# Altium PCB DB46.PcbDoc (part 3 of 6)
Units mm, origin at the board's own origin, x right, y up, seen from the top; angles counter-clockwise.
Board outline 82.2 x 113.2 mm, 8 copper layers (Top Layer, MidLayer1, MidLayer2, GND, MidLayer3, VCC, MidLayer4, Bottom Layer), stack 1.576 mm thick; 186 components, 477 nets, 1727 pads, 1538 vias.
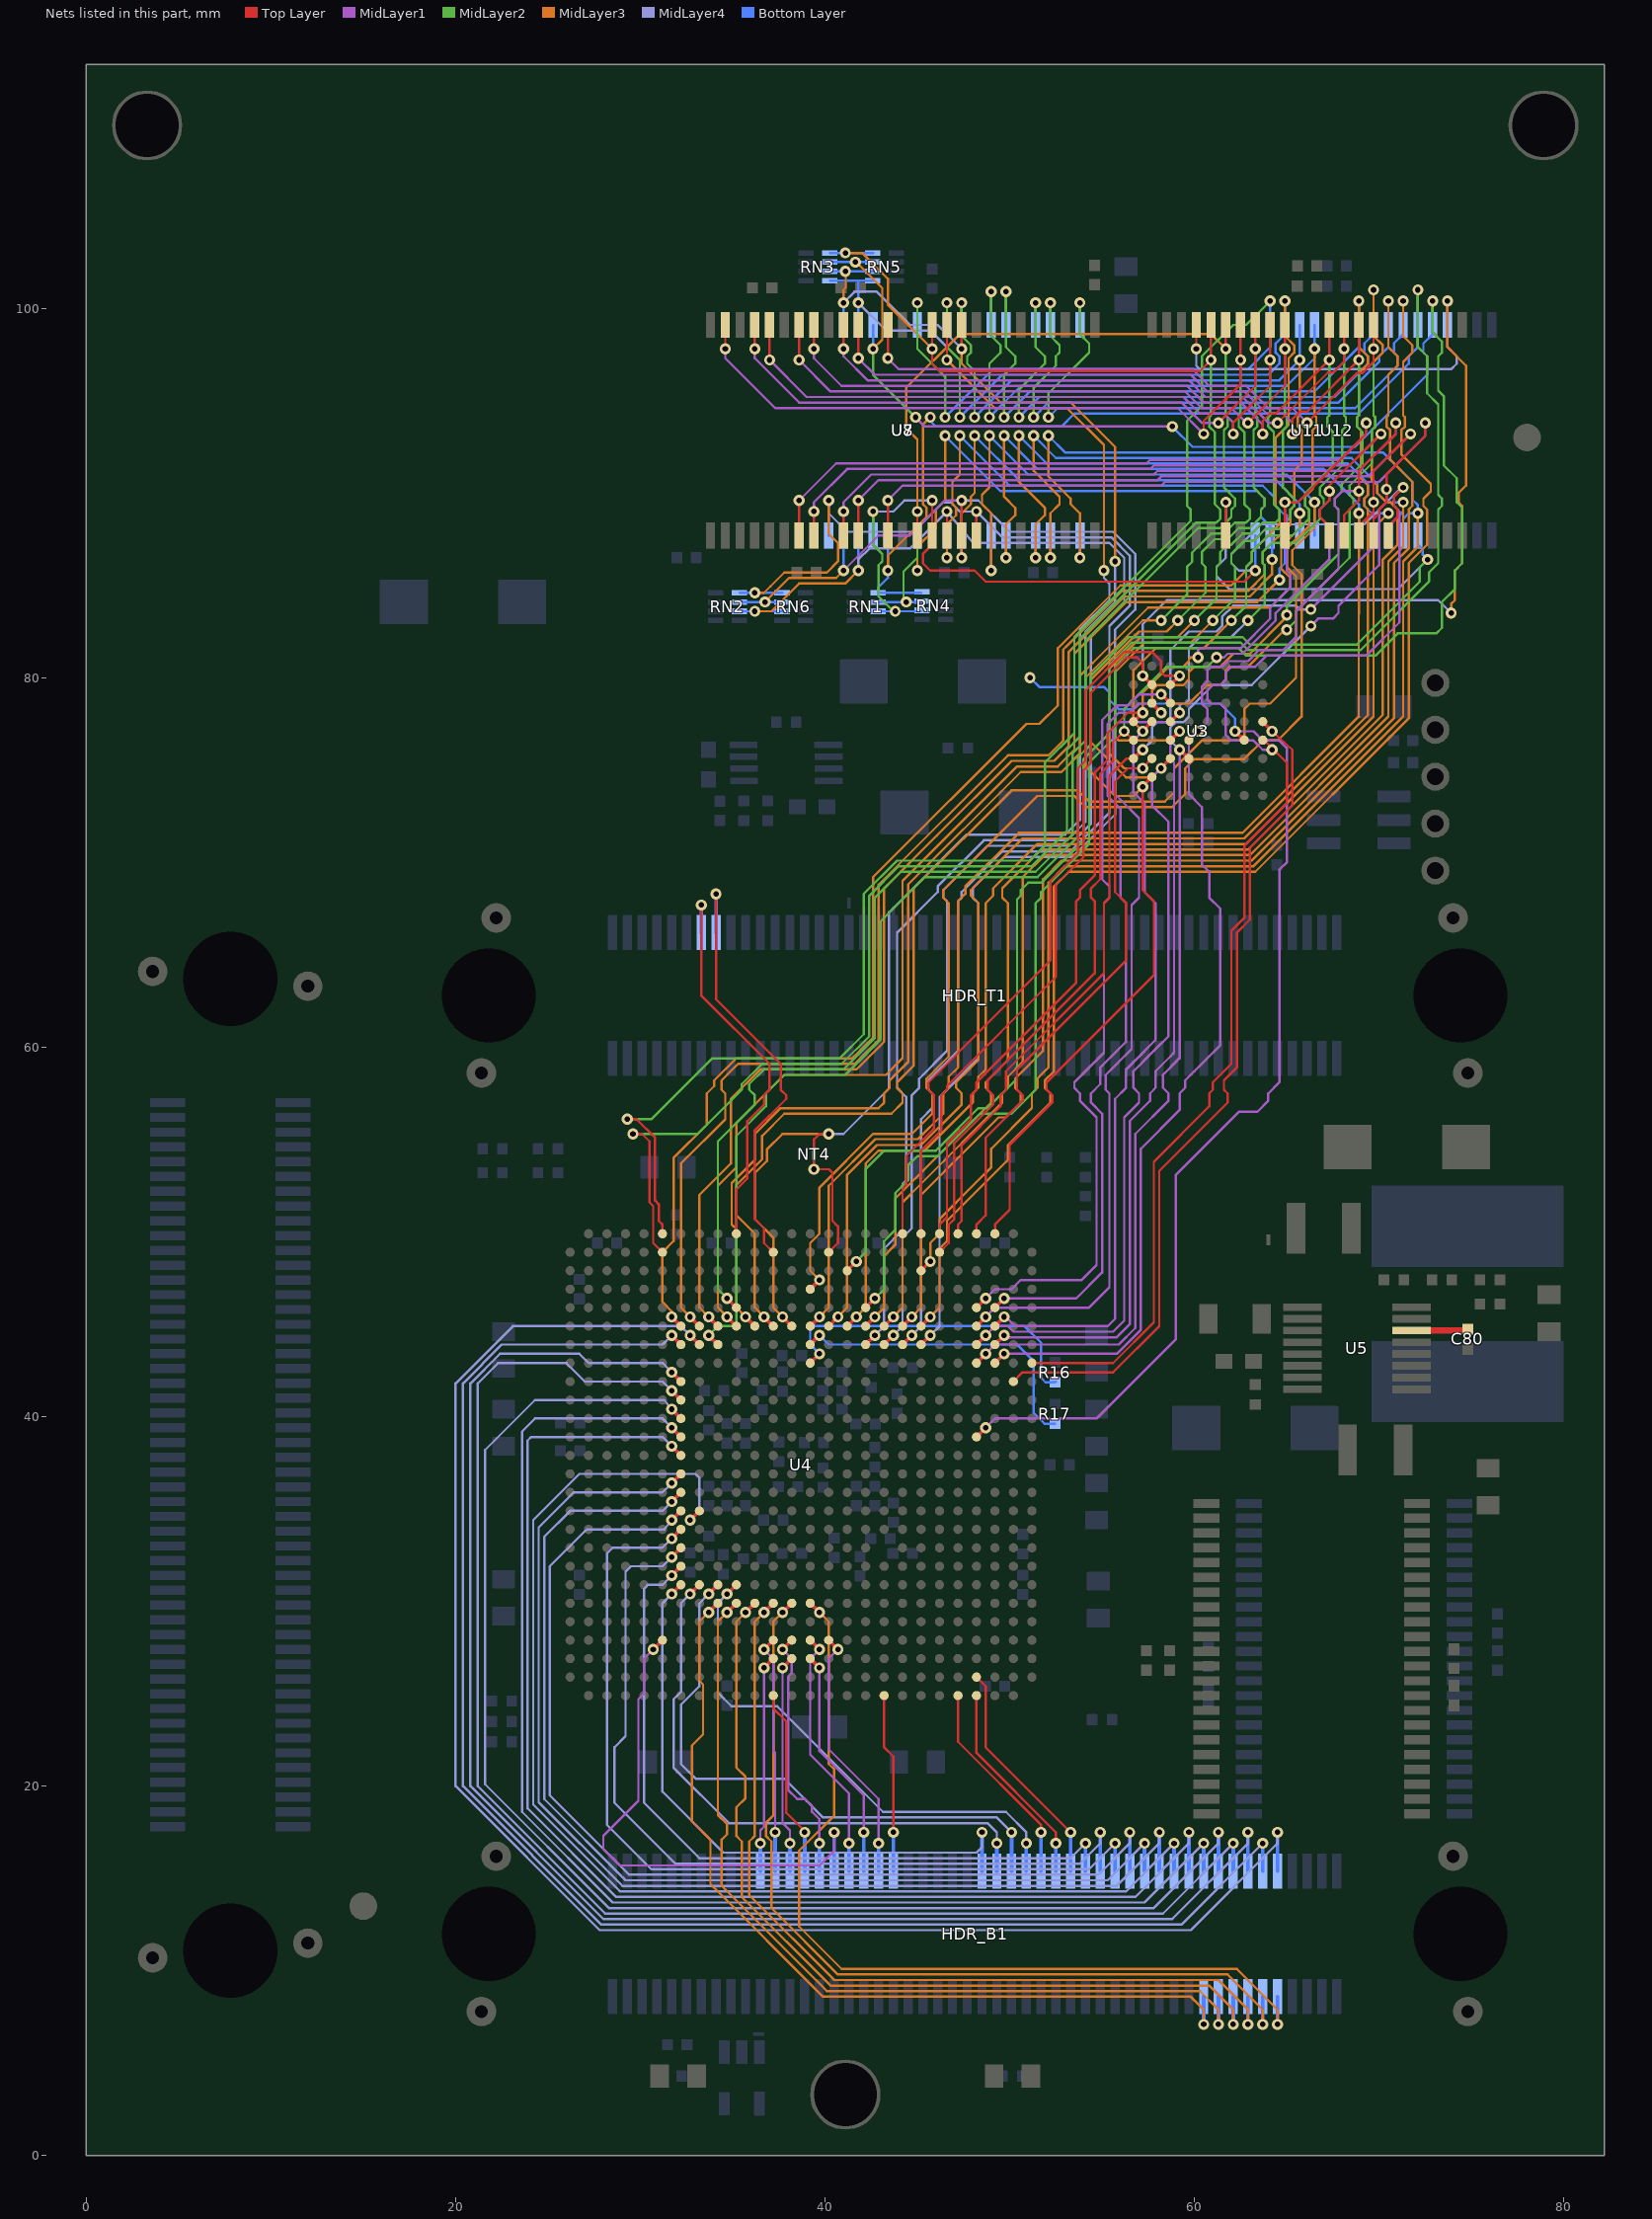
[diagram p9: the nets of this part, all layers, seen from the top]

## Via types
v1: diameter 0.6, hole 0.3, Top Layer to Bottom Layer, 904 vias
v2: diameter 0.6, hole 0.3, Top Layer to Bottom Layer, tented both sides, 506 vias
v3: diameter 0.7, hole 0.4, Top Layer to Bottom Layer, 127 vias
v4: diameter 0.6, hole 0.3, Top Layer to Bottom Layer, tented top, 1 vias

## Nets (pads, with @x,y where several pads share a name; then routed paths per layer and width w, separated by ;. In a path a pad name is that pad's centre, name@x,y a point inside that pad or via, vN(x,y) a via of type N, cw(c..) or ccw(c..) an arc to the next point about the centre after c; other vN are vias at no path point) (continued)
BUS_D3: U3.H4 U4.A21 U7.7 U11.10 | length 93.8
  Top Layer w0.127: U7.7@38.6,87.7 v2(38.6,89.6) ; U4.A21@46.2,49.9 46.2,50.4 46.6,50.8 46.6,51.5 46.6,51.8 46.6,54.8 47.9,56.1 47.9,57.4 48.2,57.7 48.2,58.1 53.6,63.5 53.6,67.9 53.8,68.1 53.8,68.5 54.6,69.3 54.6,74.859 55.3,75.559 55.3,77 56.4,78.1 v1(57.2,78.1) ; U11.10@64.9,87.7 v1(64.9,89.5) 65.6,89.5 69.3,93.2 v2(69.3,93.8)
  Top Layer w0.2: U3.H4@56.7,77.625 v1@57.187,78.112
  MidLayer1 w0.127: v2(38.6,89.6) 40.6,91.6 57.4,91.6 57.6,91.8 67.9,91.8 69.3,93.2 v2(69.3,93.8) ; v1(60.2,81.1) 60.2,81.5 60.3,81.6 62.5,81.6 64.1,83.2 64.1,83.8 65.2,84.9 65.2,85.6 65,85.8 65,88.8 64.9,88.9 v1(64.9,89.5)
  MidLayer3 w0.127: v1(57.2,78.1) 57.2,79.2 57.3,79.3 58.6,80.6 59.4,80.6 59.7,80.9 59.7,81 59.8,81.1 v1(60.2,81.1)
BUS_D4: U3.H5 U4.B21 U7.8 U11.13 | length 94.7
  Top Layer w0.127: U7.8@39.4,87.7 v2(39.4,89) ; U4.B21@46.2,48.9 46.7,49.4 ; 46.7,49.5 46.7,49.4 ; U3.H5@56.7,76.625 v1(56.2,77.1) 55.6,76.5 55.6,75.5 54.9,74.8 54.9,69.1 54.4,68.6 54.4,68.1 54.6,67.9 54.6,64 48.8,58.2 48.8,57.7 49.1,57.4 49.1,56.9 47,54.8 47,51.8 47,51.5 47,50.7 46.7,50.4 46.7,50.3 46.7,49.4 ; U11.13@67.3,87.7 67.3,88.2 66.8,88.7 66.8,89.1 67.3,89.6 v1(67.3,90.1) 67.3,90.4 v2(70.1,93.2)
  MidLayer1 w0.127: v2(39.4,89) 39.4,89.5 41.2,91.3 57.6,91.3 57.8,91.5 68.4,91.5 v2(70.1,93.2) ; v1(61.2,81.1) 61.6,81.1 61.8,81.3 62.6,81.3 64.4,83.1 64.4,83.5 67.3,86.4 67.3,88.2 66.8,88.7 66.8,89.1 67.3,89.6 v1(67.3,90.1)
  MidLayer2 w0.127: v1(56.2,77.1) 56.2,78.3 58.5,80.6 60.7,80.6 v1(61.2,81.1)
BUS_D5: U3.E5 U4.H24 U7.10 U11.14 | length 104.8
  Top Layer w0.127: U7.10@41,87.7 v2(41,89) ; U11.14@68.1,87.7 68.1,88.8 68.9,89.6 68.9,91.2 70.9,93.2 v2(70.9,93.8)
  Top Layer w0.2: U4.H24@49.2,42.9 v1(49.7,43.4) ; U3.E5@59.7,76.625 v1(60.2,77.1)
  MidLayer1 w0.127: v2(41,89) 41,89.5 42.5,91 57.8,91 58,91.2 68.9,91.2 70.9,93.2 v2(70.9,93.8) ; v1(49.7,43.4) 52.8,43.4 53.1,43.4 55.8,43.4 57.1,44.7 57.1,54.5 59.2,56.6 59.2,57.5 59.5,57.8 59.5,58.2 60,58.7 61.4,60.1 61.4,67.5 60.8,68.1 60.8,69.5 60.4,69.9 60.4,73 59.7,73.7 59.7,76.6 60.7,77.6 60.7,78.3 60.4,78.6 60.4,79.5 60.7,79.8 60.7,80.4 60.9,80.6 61.5,80.6 61.8,80.9 62.9,80.9 63.5,81.5 64.8,81.5 65.5,82.2 65.5,83.6 67.8,85.9 67.8,89.1 67.6,89.3 67.6,89.7 68,90.1 v1(68.9,90.1)
BUS_D6: U3.H6 U4.A22 U7.11 U11.15 | length 93
  Top Layer w0.127: U7.11@41.8,87.7 v2(41.8,89.6) ; U4.A22@47.2,49.9 47.2,50.4 47.4,50.6 47.4,51.5 47.4,51.8 47.4,54.7 49.5,56.8 49.5,57.4 49.8,57.7 49.8,58.7 55.1,64 55.1,67.8 55.4,68.1 55.4,74.7 56.325,75.625 U3.H6@56.7,75.625 ; U11.15@68.9,87.7 68.9,88.2 69.7,89 v1(69.7,89.5) 69.7,91.2 v2(71.7,93.2)
  Top Layer w0.2: U3.H6@56.7,75.625 57.187,76.112 v1@57.2,76.125
  MidLayer1 w0.127: v2(41.8,89.6) 42.9,90.7 58,90.7 58.2,90.9 69.4,90.9 v2(71.7,93.2) ; v1(66.3,83.7) 69.7,87.1 v1(69.7,89.5)
  MidLayer4 w0.127: v1(57.2,76.1) 57.7,76.6 57.7,77.3 58,77.6 58.5,77.6 58.7,77.8 58.7,81.5 59.7,82.5 61.2,82.5 61.5,82.8 61.5,83.3 62.1,83.9 65.5,83.9 65.7,83.7 v1(66.3,83.7)
BUS_D7: U3.E6 U4.H23 U7.13 U11.16 | length 104.7
  Top Layer w0.127: U7.13@43.4,87.7 v2(43.4,89.6) ; U11.16@69.7,87.7 69.7,88.6 70,88.9 70,89.1 70.4,89.5 70.4,91 72.5,93.1 v2(72.5,93.8)
  Top Layer w0.2: U4.H23@48.2,42.9 v1(48.7,43.4) ; v1@59.2,76.125 U3.E6@59.7,75.625
  MidLayer1 w0.127: v2(43.4,89.6) 44.2,90.4 58.2,90.4 58.4,90.6 70,90.6 72.5,93.1 v2(72.5,93.8) ; v1(48.7,43.4) 49.2,43.9 52.8,43.9 53.1,43.9 55.9,43.9 56.8,44.8 56.8,55.3 58.6,57.1 58.6,57.5 58.3,57.8 58.3,58.5 59.2,59.4 59.2,68.6 ; 59.2,68.1 v1(59.2,76.1) v1@59.2,76.125 ; v1(66.3,82.8) 66.7,83.2 67.5,83.2 67.8,83.5 67.8,83.9 70,86.1 70,89.1 70.4,89.5 v1(70.4,90.2)
  MidLayer4 w0.127: v1(59.2,76.1) 58.7,76.6 58.7,77.3 59,77.6 59.4,77.6 59.7,77.9 59.7,78.3 61,79.6 63.1,79.6 v1(66.3,82.8)
BUS_D8: U3.F3 U4.E23 U7.42 U11.29 | length 102.2
  Top Layer w0.127: v2(43.4,97.3) U7.42@43.4,99.1 ; v2(66.1,93.8) 68.787,96.487 69.087,96.487 69.7,97.1 v2(69.7,97.8) U11.29@69.7,99.1
  Top Layer w0.2: U4.E23@48.2,45.9 v1(48.7,46.4) ; v1@58.2,79.125 58.213,79.113 U3.F3@58.7,78.625
  MidLayer1 w0.127: v2(43.4,97.3) 44,96.7 59.9,96.7 60.8,95.8 62.8,95.8 64,94.6 65.3,94.6 v2(66.1,93.8) ; v1(48.7,46.4) 49.2,46.9 50.1,46.9 50.6,47.4 52.8,47.4 53.1,47.4 53.9,47.4 54.7,48.2 54.7,56.2 53.8,57.1 53.8,57.5 53.5,57.8 53.5,58.1 54.6,59.2 55.1,59.7 55.1,67.8 55.4,68.1 55.4,68.7 55,69.1 55,77.7 55.8,78.5 56.4,78.5 57,79.1 v1(58.2,79.1)
  MidLayer2 w0.127: v1(65,82.6) 65.5,83.1 65.5,83.6 68.4,86.5 68.4,89.1 68.6,89.3 68.6,89.7 68.4,89.9 68.4,90.4 69.6,91.6 69.6,93.4 69.8,93.6 69.8,94.1 69.7,94.2 v2(69.7,97.8)
  MidLayer3 w0.127: v1(58.2,79.1) 58.7,78.6 59.7,78.6 60.7,79.6 61.4,79.6 61.7,79.9 61.7,80.4 61.9,80.6 62.9,80.6 64.9,82.6 v1(65,82.6)
BUS_D9: U3.G3 U4.E24 U7.44 U11.30 | length 103.5
  Top Layer w0.127: v2(41.8,97.3) U7.44@41.8,99.1 ; v2(65.3,93.2) 65.3,94 65.7,94.4 66.1,94.4 v2(68.9,97.2) U11.30@68.9,99.1
  Top Layer w0.2: U4.E24@49.2,45.9 v1(49.7,46.4) ; U3.G3@57.7,78.625 v1(58.2,78.1)
  MidLayer1 w0.127: v2(41.8,97.3) 42.7,96.4 59.8,96.4 60.7,95.5 62.712,95.5 63.912,94.3 64.8,94.3 65.3,93.8 v2(65.3,93.2) ; v1(49.7,46.4) 52.8,46.4 53.1,46.4 53.6,46.4 55,47.8 55,56.4 54.4,57 54.4,57.5 54.9,58 54.9,58.9 56.3,60.3 56.3,67.8 56,68.1 56,72.9 55.6,73.3 55.3,73.6 55.3,77.5 55.9,78.1 56.5,78.1 57,78.6 57.7,78.6 v1(58.2,78.1)
  MidLayer2 w0.127: v1(65,83.4) 65,83.9 67.8,86.7 67.8,89.1 67.6,89.3 67.6,89.7 67.975,90.075 67.975,90.475 69.1,91.6 69.1,93.3 68.8,93.6 68.8,94.1 68.9,94.2 v2(68.9,97.2)
  MidLayer3 w0.127: v1(58.2,78.1) 57.7,78.6 57.7,79.3 58,79.6 59.4,79.6 59.7,79.9 59.7,80.3 60,80.6 61.4,80.6 62.1,81.3 63,81.3 65,83.3 v1(65,83.4)
BUS_D10: U3.F4 U4.F23 U7.45 U11.31 | length 103.7
  Top Layer w0.127: v2(41,97.8) U7.45@41,99.1 ; v2@64.45,93.85 64.55,93.85 67.225,96.525 67.525,96.525 68.1,97.1 U11.31@68.1,99.1
  Top Layer w0.2: U4.F23@48.2,44.9 v1(48.7,45.4) ; U3.F4@58.7,77.625 v1(59.2,78.1)
  MidLayer1 w0.127: v2(41,97.8) 41,97.4 42.3,96.1 59.7,96.1 60.6,95.2 62.6,95.2 64,93.8 v2(64.5,93.8) ; v1(48.7,45.4) 49.2,45.9 52.8,45.9 53.1,45.9 54.3,45.9 55.4,47 55.4,57.5 55.2,57.7 55.2,58.5 56.6,59.9 56.6,67.5 56.6,67.7 57,68.1 57,72.4 56,73.4 55.6,73.8 55.6,77.3 55.9,77.6 58.7,77.6 v1(59.2,78.1)
  MidLayer2 w0.127: v1(62.9,83.1) 63.8,84 63.8,86.1 63.7,86.2 63.7,86.8 64.2,87.3 65.5,87.3 66.8,88.6 66.8,89.1 67,89.3 67,89.7 66.8,89.9 66.8,90.3 68,91.5 68,93.4 68.2,93.6 68.2,94.1 68.1,94.2 v2(68.1,97.8)
  MidLayer4 w0.127: v1(59.2,78.1) 59.2,78.5 59.3,78.6 59.5,78.6 59.7,78.8 59.7,81.6 60.3,82.2 62,82.2 v1(62.9,83.1)
BUS_D11: U3.G4 U4.F24 U7.47 U11.32 | length 104.3
  Top Layer w0.127: v2(39.4,97.8) U7.47@39.4,99.1 ; v2(63.7,93.2) 63.7,93.9 64.1,94.3 64.4,94.3 v2(67.3,97.2) U11.32@67.3,99.1
  Top Layer w0.2: U4.F24@49.2,44.9 v1(49.7,45.4) ; v1(57.2,77.1) U3.G4@57.7,77.625
  MidLayer1 w0.127: v2(39.4,97.8) 39.4,97.3 40.9,95.8 59.6,95.8 60.5,94.9 62.5,94.9 63.7,93.7 v2(63.7,93.2) ; v1(49.7,45.4) 49.8,45.4 50.3,44.9 52.8,44.9 53.1,44.9 55.3,44.9 55.7,45.3 55.7,57.2 56.3,57.8 56.3,58.8 56.7,59.2 57.9,60.4 57.9,67.8 57.3,68.4 57.3,73.2 56.7,73.8 56.7,76.6 v1(57.2,77.1)
  MidLayer2 w0.127: v1(62,83.1) 62.8,83.9 62.8,86 63.1,86.3 63.1,86.8 64,87.7 65.3,87.7 66.2,88.6 66.2,89.1 66,89.3 66,90 67.5,91.5 67.5,93.3 67.2,93.6 67.2,94.1 67.3,94.2 v2(67.3,97.2)
  MidLayer3 w0.127: v1(57.2,77.1) 56.7,77.6 56.7,80.4 57.9,81.6 60.5,81.6 v1(62,83.1)
BUS_D12: U3.F5 U4.G24 U7.48 U11.35 | length 107.4
  Top Layer w0.127: v2(38.6,97.2) U7.48@38.6,99.1 ; v2(62.9,93.8) 64.9,95.8 v2(64.9,97.8) U11.35@64.9,99.1
  Top Layer w0.2: U4.G24@49.2,43.9 v1(49.7,44.4) ; U3.F5@58.7,76.625 v1(59.2,77.1)
  MidLayer1 w0.127: v2(38.6,97.2) 40.3,95.5 59.5,95.5 60.4,94.6 62,94.6 62.8,93.8 v2(62.9,93.8) ; v1(49.7,44.4) 49.8,44.3 52.8,44.3 53.1,44.3 55.8,44.3 56.5,45 56.5,56 57.6,57.1 57.6,57.5 57.9,57.8 57.9,58.7 58.7,59.5 58.9,59.7 58.9,75.4 58.7,75.6 58.7,76.6 v1(59.2,77.1) v1@59.1,77.2
  MidLayer2 w0.127: v1(61,83.1) 62.2,84.3 62.2,86 62,86.2 62,86.7 62.7,87.4 63.2,87.4 63.85,88.05 64.55,88.05 65.2,88.7 65.2,89.1 65.4,89.3 65.4,89.7 64.8,90.3 64.8,93.4 65,93.6 65,94.1 64.9,94.2 v2(64.9,97.8)
  MidLayer3 w0.127: v1(59.2,77.1) 58.7,76.6 55.9,76.6 55.7,76.8 55.7,80.3 57.3,81.9 59.8,81.9 v1(61,83.1)
  Bottom Layer w0.381: v1@49.7,44.292 v1(49.7,44.4)
BUS_D13: U3.G6 U4.A23 U7.50 U11.36 | length 96.5
  Top Layer w0.127: v2(37,97.2) U7.50@37,99.1 ; U4.A23@48.2,49.9 48.2,50.4 48.7,50.9 48.7,51.5 48.7,51.8 48.7,55.1 50.7,57.1 50.7,57.4 50.4,57.7 50.4,58.8 56.3,64.7 56.3,67.8 55.7,68.4 55.7,72.1 ; 55.7,71.7 55.7,74.4 56.4,75.1 v1(57.2,75.1) ; v1@57.2,75.125 U3.G6@57.7,75.625 ; v2(62.1,93.2) 62.1,93.8 64.1,95.8 v2(64.1,97.2) U11.36@64.1,99.1
  MidLayer1 w0.127: v2(37,97.2) 39,95.2 59.4,95.2 60.3,94.3 61.6,94.3 62.1,93.8 v2(62.1,93.2)
  MidLayer2 w0.127: v1(60,83.1) 61.2,84.3 61.2,86 61.4,86.2 61.4,86.8 61.8,87.2 62,87.2 62.6,87.8 63.1,87.8 63.7,88.4 64.1,88.4 64.4,88.4 64.6,88.6 64.6,89.1 64.3,89.4 64.3,93.3 64,93.6 64,94.1 64.1,94.2 v2(64.1,97.2)
  MidLayer3 w0.127: v1(57.2,75.1) 56.2,75.1 55.4,75.9 55.4,80.5 57.1,82.2 59.1,82.2 v1(60,83.1)
BUS_D14: U3.F6 U4.G23 U7.51 U11.37 | length 107.9
  Top Layer w0.127: v2(36.2,97.8) U7.51@36.2,99.1 ; v2(61.3,93.8) 63.3,95.8 v2(63.3,97.8) U11.37@63.3,99.1
  Top Layer w0.2: U4.G23@48.2,43.9 v1(48.7,44.4) ; v1@58.187,75.112 U3.F6@58.7,75.625
  MidLayer1 w0.127: v2(36.2,97.8) 36.2,97.3 38.6,94.9 59.3,94.9 60.4,93.8 v2(61.3,93.8) ; v1(48.7,44.4) 49.2,44.9 49.9,44.9 50.2,44.6 52.8,44.6 53.1,44.6 55.6,44.6 56.2,45.2 56.2,56.2 57,57 57,57.5 56.7,57.8 56.7,58.7 57.8,59.8 58.6,60.6 58.6,72.2 57.7,73.1 57.7,74.6 v1(58.2,75.1) v1@58.2,75.125
  MidLayer2 w0.127: v1(59.1,83.1) 60.6,84.6 60.6,86 60.4,86.2 60.4,86.8 61.1,87.5 61.8,87.5 62.4,88.1 63,88.1 63.6,88.7 63.6,89.1 63.8,89.3 63.8,89.7 63.2,90.3 63.2,93.4 63.4,93.6 63.4,94.1 63.3,94.2 v2(63.3,97.8)
  MidLayer3 w0.127: v1(58.2,75.1) 57.7,74.6 56.3,74.6 54.4,76.5 54.4,79.9 57,82.5 58.5,82.5 v1(59.1,83.1)
BUS_D15: U3.G7 U4.A24 U7.53 U11.38 | length 96.5
  Top Layer w0.127: v2(34.6,97.8) U7.53@34.6,99.1 ; U4.A24@49.2,49.9 49.2,50.4 50,51.2 50,51.5 50,51.8 50,54.7 52.3,57 52.3,57.4 52,57.7 52,58.1 57.8,63.9 57.8,67.9 57.2,68.5 57.2,71.606 ; 57.2,71.5 v1(57.2,74.1) v1@57.2,74.125 ; v2(60.5,93.2) 60.5,93.9 62.5,95.9 v2(62.5,97.2) U11.38@62.5,99.1
  Top Layer w0.2: v1@57.2,74.125 U3.G7@57.7,74.625
  MidLayer1 w0.127: v2(34.6,97.8) 34.6,97.3 37.3,94.6 59.1,94.6 v2(60.5,93.2)
  MidLayer2 w0.127: v1(58.2,83.1) 59.6,84.5 59.6,86 59.875,86.275 59.875,86.775 60.9,87.8 61.6,87.8 62.2,88.4 62.8,88.4 63,88.6 63,89.1 62.7,89.4 62.7,93.3 62.4,93.6 62.4,94.1 62.5,94.2 v2(62.5,97.2)
  MidLayer3 w0.127: v1(57.2,74.1) 56.7,73.6 55.7,73.6 54.1,75.2 54.1,80 57.2,83.1 v1(58.2,83.1)
BUS_D16: U4.C20 U8.2 U12.7 | length 91
  Top Layer w0.178: U4.C20@45.2,47.9 v1(45.7,48.4)
  MidLayer3 w0.127: v1(45.7,48.4) 45.7,49.4 46.2,49.9 46.2,50.7 48.1,52.6 49,53.5 49,54.5 51.2,56.7 51.2,57.5 51.5,57.8 51.5,58.3 52.1,58.9 52.1,68.9 53,69.8 63.2,69.8 71.3,77.9 71.3,86.3 72.1,87.1 v2(72.1,88.9) ; v2(52.1,93.1) 52.1,90.9 53.3,89.7 53.3,89.4 53.8,88.9 v2(53.8,86.5)
  Bottom Layer w0.127: v2(52.1,93.1) 53,92.2 70.2,92.2 71.8,90.6 71.8,89.65 72.1,89.35 v2(72.1,88.9) 71.6,88.9 71.3,88.6 U12.7@71.3,87.7 ; v2(53.8,86.5) U8.2@53.8,87.7
BUS_D17: U4.F18 U8.4 U12.8 | length 95.2
  Top Layer w0.2: U4.F18@43.2,44.9 v1(43.7,45.4)
  MidLayer3 w0.127: v1(43.7,45.4) 44.2,45.9 44.2,51.5 44.2,51.6 45.2,52.6 49.6,57 49.6,57.5 49.9,57.8 49.9,58.4 50.7,59.2 50.7,69.2 51.9,70.4 63,70.4 70.5,77.9 70.5,86.3 71.3,87.1 v2(71.3,89.5) ; v2(51.3,93.1) 51.3,91.2 52.7,89.8 52.7,89.4 52.2,88.9 v2(52.2,86.5)
  Bottom Layer w0.127: v2(51.3,93.1) 52.5,91.9 68.5,91.9 69.9,90.5 69.9,90 70.4,89.5 v2(71.3,89.5) 71.3,89 70.5,88.2 U12.8@70.5,87.7 ; v2(52.2,86.5) U8.4@52.2,87.7
BUS_D18: U4.F16 U8.5 U12.9 | length 96.7
  Top Layer w0.2: U4.F16@41.2,44.9 v1(41.7,45.4)
  MidLayer3 w0.127: v1(41.7,45.4) 42.2,45.9 42.2,51.5 42.2,51.8 42.2,53.7 42.9,54.4 45.4,54.4 48,57 48,57.5 48.3,57.8 48.3,58.4 48.7,58.8 48.7,67.8 49.1,68.2 49.1,68.6 51.5,71 62.8,71 69.7,77.9 69.7,88.1 v2(70.5,88.9) ; v2(50.5,93.1) 50.5,90.6 51.888,89.212 51.9,89.212 51.9,88.8 51.4,88.3 v2(51.4,86.5)
  Bottom Layer w0.127: v2(50.5,93.1) 52,91.6 68.3,91.6 69.4,90.5 69.4,89.9 69.2,89.7 69.2,89.3 69.6,88.9 69.7,88.9 ; v2(51.4,86.5) U8.5@51.4,87.7 ; U12.9@69.7,87.7 69.7,88.9 ; v2(70.5,88.9) 69.7,88.9
BUS_D19: U4.F14 U8.7 U12.10 | length 95.4
  Top Layer w0.2: U4.F14@39.2,44.9 v1(39.7,45.4)
  MidLayer3 w0.127: v1(39.7,45.4) 40.2,45.9 40.2,51.5 40.2,51.8 40.2,52.5 42.725,55.025 45.025,55.025 46.4,56.4 46.4,57.5 46.7,57.8 46.7,58.4 47.2,58.9 47.2,67.9 47.6,68.3 47.6,68.7 50.5,71.6 62.6,71.6 68.9,77.9 ; v2(49.7,93.1) 49.7,89.8 50.3,89.2 50.3,88.8 49.8,88.3 v2(49.8,86.5) ; 68.896,77.9 v2(68.9,88.9)
  Bottom Layer w0.127: v2(49.7,93.1) 51.5,91.3 67,91.3 68.9,89.4 v2(68.9,88.9) U12.10@68.9,87.7 ; v2(49.8,86.5) U8.7@49.8,87.7
BUS_D20: U4.D14 U8.8 U12.13 | length 94.1
  Top Layer w0.2: U4.D14@39.2,46.9 v1(39.7,47.4)
  MidLayer3 w0.127: v1(39.7,47.4) 39.2,47.9 39.2,49.4 39.7,49.9 39.7,51.5 39.7,51.8 39.7,52.4 42.6,55.3 44.7,55.3 45.8,56.4 45.8,57.5 45.5,57.8 45.5,58.3 46.7,59.5 46.7,67.8 46.4,68.1 46.4,68.5 51.5,73.6 53.5,73.6 54.1,73 58.8,73 59.5,73.7 59.5,75.1 60,75.6 62.7,75.6 63.7,76.6 64.5,76.6 65.8,77.9 65.8,85.6 65.3,86.1 65.3,86.9 66.5,88.1 v2(66.5,89.5) ; v2(48.9,93.1) 48.9,90.3 48.5,89.9 48.5,89.4 49,88.9 v2(49,85.8)
  Bottom Layer w0.127: v2(48.9,93.1) 51,91 65,91 v2(66.5,89.5) 66.5,88.9 U12.13@66.5,87.7 ; v2(49,85.8) U8.8@49,87.7
BUS_D21: U4.F11 U8.10 U12.14 | length 94.9
  Top Layer w0.2: v1(35.7,45.4) U4.F11@36.2,44.9
  MidLayer3 w0.127: v1(35.7,45.4) 35.2,45.9 35.2,50.142 34.946,50.396 34.946,52.646 36.2,53.9 36.2,55.3 37.6,56.7 42.9,56.7 43.2,57 43.2,57.5 43.5,57.8 43.5,58.2 44.5,59.2 44.5,68.8 50.6,74.9 52.8,74.9 53.8,75.9 53.8,80.1 54.5,80.8 57.5,83.8 64.1,83.8 65.2,84.9 65.2,85.4 64.7,85.9 64.7,87.1 65.7,88.1 v2(65.7,88.9) ; v2(47.4,86.5) 47.4,88.9 47.9,89.4 47.9,89.8 48.1,90 v2(48.1,93.1)
  Bottom Layer w0.127: v2(47.4,86.5) U8.10@47.4,87.7 ; v2(48.1,93.1) 50.5,90.7 64.4,90.7 65.7,89.4 v2(65.7,88.9) U12.14@65.7,87.7
BUS_D22: U4.F10 U8.11 U12.15 | length 93.6
  Top Layer w0.2: v1(34.7,45.4) U4.F10@35.2,44.9
  MidLayer3 w0.127: v1(34.7,45.4) 34.2,45.9 34.2,51.5 34.2,51.8 34.2,52.5 35.2,53.5 35.2,55.9 37.8,58.5 43.3,58.5 44.2,59.4 44.2,69 50.4,75.2 52.6,75.2 53.5,76.1 53.5,81.3 56.3,84.1 63.4,84.1 v1(64.6,85.3) ; v2(46.6,86.5) 46.6,88.3 47.1,88.8 47.1,89.2 46.9,89.4 46.9,90.6 47.3,91 v2(47.3,93.1)
  Bottom Layer w0.127: v2(46.6,86.5) U8.11@46.6,87.7 ; v2(47.3,93.1) 50,90.4 63.7,90.4 64.4,89.7 64.4,89.3 64.9,88.8 U12.15@64.9,87.7 64.9,86.8 64.9,86.2 64.6,85.9 v1(64.6,85.3)
BUS_D23: U4.F9 U8.13 U12.16 | length 95.6
  Top Layer w0.2: v1(33.7,45.4) U4.F9@34.2,44.9
  MidLayer3 w0.127: v1(33.7,45.4) 33.2,45.9 33.2,51.5 33.2,51.8 33.2,52 34.9,53.7 34.9,57.2 36.5,58.8 41.7,58.8 43.2,60.3 43.2,68.6 46.05,71.45 50.1,75.5 52.4,75.5 53.2,76.3 53.2,81.4 56.2,84.4 63,84.4 64.2,85.6 64.2,85.9 ; v2(45,85.8) 45,87.1 46,88.1 46,89.1 46.5,89.6 v2(46.5,93.1) ; 64.2,85.594 v2(64.2,86.4)
  Bottom Layer w0.127: v2(45,85.8) U8.13@45,87.7 ; v2(46.5,93.1) 49.5,90.1 63.4,90.1 63.8,89.7 63.8,89.3 63.6,89.1 63.6,88.7 64.1,88.2 U12.16@64.1,87.7 64.2,87.6 v2(64.2,86.4)
BUS_D24: U4.A6 U8.42 U12.29 | length 105.3
  Top Layer w0.127: v1(29.3,56.1) 29.8,56.1 30.8,55.1 30.8,51.7 31,51.5 31,50.6 31.2,50.4 ; U4.A6@31.2,49.9 31.2,50.4
  MidLayer2 w0.127: v1(29.3,56.1) 30.6,56.1 33.9,59.4 40.8,59.4 42.1,60.7 42.1,68.3 43.9,70.1 51.1,70.1 51.9,70.9 51.9,75.4 53.5,77 53.5,82.2 59.8,88.5 59.8,89.1 59.6,89.3 59.6,93.9 60.4,94.7 60.4,97.4 62.1,99.1 62.808,99.1 v2(64.1,100.391) ; v2(45,100.3) 45,97.8 46.5,96.3 v2(46.5,94.1)
  Bottom Layer w0.127: U8.42@45,99.1 v2(45,100.3) ; v2(46.5,94.1) 49.1,96.7 62.9,96.7 64.1,97.9 v2(64.1,100.391)
BUS_D25: U4.F7 U8.44 U12.30 | length 107.9
  Top Layer w0.2: v1(31.7,45.4) U4.F7@32.2,44.9
  MidLayer2 w0.127: v2(46.6,100.3) 46.6,97.9 47.3,97.2 v2(47.3,94.1)
  MidLayer3 w0.127: v1(31.7,45.4) 31.7,45.7 31.2,46.2 31.2,48.9 31.8,49.5 31.8,54 33.6,55.8 33.6,57.5 34,57.9 34,58.2 35.2,59.4 41.5,59.4 42.6,60.5 42.6,69.2 50.9,77.5 51.6,77.5 52.6,78.5 52.6,81.6 56,85 62,85 62.8,85.8 62.8,86 63.1,86.3 63.1,86.8 63.25,86.95 64.6,88.3 64.6,89.1 64.4,89.3 64.4,93 65.1,93.7 65.1,97.3 65.4,97.6 65.4,98 64.9,98.5 v2(64.9,100.4)
  Bottom Layer w0.127: U8.44@46.6,99.1 v2(46.6,100.3) ; v2(47.3,94.1) 49.6,96.4 64,96.4 64.6,97 64.6,97.4 64.4,97.6 64.4,98.1 64.9,98.6 v2(64.9,100.4)
BUS_D26: U4.F8 U8.45 U12.31 | length 104.6
  Top Layer w0.2: v1(32.7,45.4) U4.F8@33.2,44.9
  MidLayer2 w0.127: v2(47.4,100.3) 47.4,98.5 47.9,98 47.9,97.6 47.7,97.4 47.7,97 48.1,96.6 v2(48.1,94.1)
  MidLayer3 w0.127: v1(32.7,45.4) 32.2,45.9 32.2,51.5 32.2,51.8 32.2,53.7 34.6,56.1 34.6,57.5 34.4,57.7 34.4,58.2 35.3,59.1 41.6,59.1 42.9,60.4 42.9,68.8 49.9,75.8 52.1,75.8 52.9,76.6 52.9,81.525 53.075,81.7 56.075,84.7 62.9,84.7 63.8,85.6 63.8,86.1 63.7,86.2 63.7,86.8 65.2,88.3 65.2,89.1 65.4,89.3 65.4,91.2 65.8,91.6 65.8,93.4 65.6,93.6 65.6,94.1 65.7,94.2 v2(65.7,97.2)
  Bottom Layer w0.127: U8.45@47.4,99.1 v2(47.4,100.3) ; v2(48.1,94.1) 50.1,96.1 64.6,96.1 v2(65.7,97.2) U12.31@65.7,99.1
BUS_D27: U4.F12 U8.47 U12.32 | length 108.5
  Top Layer w0.2: v1(36.7,45.4) U4.F12@37.2,44.9
  MidLayer2 w0.127: v2(48.9,94.1) 48.9,97 49.5,97.6 49.5,98 49,98.5 v2(49,100.9)
  MidLayer3 w0.127: v1(36.7,45.4) 36.2,45.9 36.2,49.908 35.2,50.908 35.2,52.541 36.6,53.941 36.6,55.2 37.8,56.4 43.6,56.4 44.2,57 ; 44.1,56.9 44.2,57 ; v2(66.5,97.8) 66.5,94.2 66.6,94.1 66.6,93.6 66.4,93.4 66.4,90.2 66,89.8 66,89.3 66.2,89.1 66.2,88.2 65,87 65,86 65.5,85.5 65.5,80 64.1,78.6 63,78.6 62.7,78.3 62.7,76.9 62.4,76.6 60.4,76.6 58.9,75.1 58.9,73.8 58.4,73.3 54.3,73.3 53.7,73.9 50.1,73.9 44.8,68.6 44.8,59 43.9,58.1 43.9,57.8 44.2,57.5 44.2,57
  Bottom Layer w0.127: v2(48.9,94.1) 50.6,95.8 65,95.8 66.5,97.3 v2(66.5,97.8) U12.32@66.5,99.1 ; U8.47@49,99.1 v2(49,100.9)
BUS_D28: U4.F15 U8.48 U12.35 | length 109.9
  Top Layer w0.2: U4.F15@40.2,44.9 v1(40.7,45.4)
  MidLayer2 w0.127: v2(49.7,94.1) 49.7,96.4 50.3,97 50.3,97.4 49.8,97.9 v2(49.8,100.9)
  MidLayer3 w0.127: v1(40.7,45.4) 41.2,45.9 41.2,51.5 41.2,51.8 41.2,53.1 42.8,54.7 45.2,54.7 47.4,56.9 47.4,57.5 47.1,57.8 47.1,58.1 48.3,59.3 48.3,67.8 47.9,68.2 47.9,68.5 50.7,71.3 62.7,71.3 69.4,78 69.4,89.1 69.2,89.3 69.2,89.7 69.4,89.9 69.4,90.4 69,90.8 69,93.4 68.8,93.6 68.8,94.1 68.9,94.2 68.9,96.5 69.4,97 69.4,97.4 68.9,97.9 v2(68.9,100.4)
  Bottom Layer w0.127: v2(49.7,94.1) 51.1,95.5 66.5,95.5 68.9,97.9 68.9,99.1 v2(68.9,100.4) ; v2@49.7,100.9 v2(49.8,100.9) U8.48@49.8,99.1
BUS_D29: U4.F17 U8.50 U12.36 | length 108.9
  Top Layer w0.2: U4.F17@42.2,44.9 v1(42.7,45.4)
  MidLayer2 w0.127: v2(50.5,94.1) 50.5,95.6 51.9,97 51.9,97.4 51.4,97.9 v2(51.4,100.3)
  MidLayer3 w0.127: v1(42.7,45.4) 43.2,45.9 43.2,48.7 43.8,49.3 43.8,51.5 43.8,51.8 44.9,52.9 49,57 49,57.5 48.7,57.8 48.7,58.1 49.9,59.3 49.9,67.8 49.6,68.1 49.6,68.6 51.7,70.7 62.9,70.7 70.2,78 70.2,86.4 71,87.2 71,89.1 70.6,89.5 70.4,89.5 69.9,90 69.9,90.4 69.6,90.7 69.6,93.4 69.8,93.6 69.8,94.1 69.7,94.2 69.7,97.1 70.2,97.6 70.2,98 69.7,98.5 v2(69.7,101)
  Bottom Layer w0.127: v2(50.5,94.1) 51.6,95.2 67.6,95.2 69.4,97 69.4,97.4 69.2,97.6 69.2,98.1 69.7,98.6 69.7,99.1 v2(69.7,101) ; U8.50@51.4,99.1 v2(51.4,100.3)
BUS_D30: U4.F19 U8.51 U12.37 | length 106.1
  Top Layer w0.2: U4.F19@44.2,44.9 v1(44.7,45.4)
  MidLayer2 w0.127: v2(51.3,94.1) 51.3,95.7 52.5,96.9 52.5,97.4 52.7,97.6 52.7,98 52.2,98.5 v2(52.2,100.3)
  MidLayer3 w0.127: v1(44.7,45.4) 45.2,45.9 45.2,51.5 45.2,51.8 45.2,52 49.4,56.2 49.8,56.2 50.6,57 50.6,57.5 50.3,57.8 50.3,58.3 51.8,59.8 51.8,69.1 52.8,70.1 63.1,70.1 70.8,77.8 70.8,86.2 71.6,87 71.6,89.1 71.8,89.3 71.8,90.6 70.6,91.8 70.6,93.4 70.4,93.6 70.4,94.1 70.5,94.2 70.5,96.4 71,96.9 71,97.4 70.5,97.9 v2(70.5,100.4)
  Bottom Layer w0.127: v2(51.3,94.1) 52.1,94.9 67.8,94.9 70,97.1 70,97.4 70.5,97.9 70.5,99.1 v2(70.5,100.4) ; U8.51@52.2,99.1 v2(52.2,100.3)
BUS_D31: U4.F20 U8.53 U12.38 | length 106.8
  Top Layer w0.2: U4.F20@45.2,44.9 v1(45.7,45.4)
  MidLayer2 w0.127: v2(52.1,94.1) 52.1,95.4 54.3,97.6 54.3,98.1 53.8,98.6 v2(53.8,100.3)
  MidLayer3 w0.127: v1(45.7,45.4) 46.2,45.9 46.2,49.1 46.6,49.5 46.6,50.6 49.9,53.9 49.9,54.7 52.2,57 52.2,57.5 51.9,57.8 51.9,58.2 52.4,58.7 52.4,68.7 53.2,69.5 63.3,69.5 71.6,77.8 71.6,86.2 72.6,87.2 72.6,89.1 72.4,89.3 72.4,89.7 72.8,90.1 72.8,90.5 71.2,92.1 71.2,93.4 71.4,93.6 71.4,94.1 71.3,94.2 71.3,97.1 71.8,97.6 71.8,98 71.3,98.5 v2(71.3,100.4)
  Bottom Layer w0.127: v2(52.1,94.1) 52.6,94.6 68.7,94.6 71,96.9 71,97.4 70.8,97.6 70.8,98.1 71.3,98.6 v2(71.3,100.4) ; U8.53@53.8,99.1 v2(53.8,100.3)
BUS_FLASH_NBUSY: U3.A4 U4.J25 | length 45.7
  Top Layer w0.127: U4.J25@50.2,41.9 50.7,42.4 52.8,42.4 53.1,42.4 55.6,42.4 58.1,44.9 58.1,53.3 61.8,57 61.8,57.5 61.6,57.7 61.6,58.2 62.3,58.9 62.3,66.2 63,66.9 63,70.8 65.3,73.1 65.3,76.1 v1(64.2,77.1)
  Top Layer w0.2: U3.A4@63.7,77.625 v1(64.2,77.1)
BUS_FLASH_NCS: U3.F2 U4.A19 | length 41.3
  Top Layer w0.127: U4.A19@44.2,49.9 44.2,51.5 44.2,51.8 44.2,52.325 44.4,52.525 44.4,54.1 45.9,55.6 45.9,57.4 45.6,57.7 45.6,58.1 52.2,64.7 52.2,69 53.7,70.5 53.7,75.1 54.1,75.5 54.1,79.3 56.2,81.4 57.7,81.4 58.2,80.9 58.2,80.3 58.4,80.1 v1(59.2,80.1) ; U3.F2@58.675,79.625 U3.F2@58.7,79.625
  Top Layer w0.2: U3.F2@58.7,79.625 v1(59.2,80.1)
BUS_FLASH_NRESET: U3.B5 U4.M23 | length 65.1
  Top Layer w0.2: U4.M23@48.2,38.9 v1(48.7,39.4) ; v1(62.2,77.1) U3.B5@62.7,76.625
  MidLayer1 w0.127: v1(48.7,39.4) 49.2,39.9 52.8,39.9 53.1,39.9 54.7,39.9 59,44.2 59,53.1 62.4,56.5 63.4,56.5 64,57.1 64,57.5 64.6,58.1 64.6,69.6 65,70 65,76.2 64.6,76.6 63.7,76.6 63.2,77.1 v1(62.2,77.1)
  Bottom Layer w0.127: v1(51.1,80) 51.6,79.5 55.1,79.5 55.4,79.2 55.4,78.8 55.9,78.3 56.7,78.3 57,78.6 61.4,78.6 62.2,77.8 v1(62.2,77.1)
BUS_NBE0: RN1.6 RN4.7 U4.E10 U7.15 U11.39 | length 107.9
  Top Layer w0.127: U7.15@45,87.7 v2(45,89) ; v2(61.7,97.8) U11.39@61.7,99.1
  Top Layer w0.2: v1(34.7,46.4) U4.E10@35.2,45.9
  MidLayer2 w0.127: v1(34.7,46.4) 34.2,46.9 34.2,51.5 34.2,51.8 34.2,54.9 36.2,56.9 36.2,57.4 35.9,57.7 35.9,58 36.7,58.8 41,58.8 42.7,60.5 42.7,68.1 44.1,69.5 51.4,69.5 53.4,71.5 53.4,75.9 54.1,76.6 54.1,82 60.2,88.1 61.4,88.1 62,88.7 62,89.1 62.2,89.3 62.2,89.7 61.6,90.3 61.6,93.4 61.8,93.6 61.8,94.1 61.7,94.2 v2(61.7,97.8) ; v1@44.25,84.1 44.25,85.75 45,86.5 v2(45,89)
  MidLayer3 w0.127: v2(45,89) 45,92.9 44.4,93.5 44.4,95.7 47.3,98.6 60.9,98.6 v2(61.7,97.8)
  Bottom Layer w0.127: RN1.6@42.89,84.1 RN4.7@45.21,84.1
  other v1: 44.4,84.1
BUS_NBE1: RN3.5 RN5.8 U4.B6 U7.39 U11.40 | length 101.7
  Top Layer w0.127: v1(29.6,55.3) 30.1,55.3 30.5,54.9 30.5,51.6 30.7,51.4 30.7,49.4 U4.B6@31.2,48.9 ; U7.39@45.8,99.1 v2(45.8,97.8) 45.8,97 46.2,96.6 60.3,96.6 v2(60.9,97.2) U11.40@60.9,99.1
  MidLayer2 w0.127: v1(29.6,55.3) 33.1,55.3 35.5,57.7 35.5,58 36.6,59.1 40.9,59.1 42.4,60.6 42.4,68.2 44,69.8 51.2,69.8 53.1,71.7 53.1,76.1 53.8,76.8 53.8,82.1 60.1,88.4 61.2,88.4 61.4,88.6 61.4,89.1 61.1,89.4 61.1,93.3 60.8,93.6 60.8,94.1 60.9,94.2 v2(60.9,97.2)
  MidLayer3 w0.127: v1@41.095,103 42,103 43.4,101.6 43.4,100.2 v2@45.8,97.8
  Bottom Layer w0.127: RN3.5@40.29,103 RN5.8@42.6,103
  other v1: 41.1,103
BUS_NBE2: RN1.5 RN4.8 U4.C16 U8.15 U12.39 | length 123.8
  Top Layer w0.178: U4.C16@41.2,47.9 v1(41.7,48.4)
  MidLayer2 w0.127: v1(41.7,48.4) 42.2,48.9 42.2,51.5 42.2,51.8 42.2,53.4 43.2,54.4 46,54.4 46.2,54.6 48.3,56.7 48.8,56.7 50.4,58.3 50.4,68 50.6,68.2 50.6,68.5 51,68.9 51.7,68.9 54,71.2 54,75.6 55.4,77 55.4,80.7 56.6,81.9 62.5,81.9 62.9,81.5 69,81.5 72.7,85.2 72.7,85.7 73.2,86.2 73.2,89.1 73.4,89.3 73.4,89.7 73.2,89.9 73.2,94.8 72.6,95.4 72.6,97.4 72.1,97.9 v2(72.1,101)
  MidLayer3 w0.127: v2(43.4,85.8) 43.4,86.6 45.5,88.7 45.5,89.2 45.3,89.4 45.3,93.7 v2(45.7,94.1)
  Bottom Layer w0.127: U8.15@43.4,87.7 v2(43.4,85.8) 43.4,85.4 42.9,84.9 42.9,84.61 42.89,84.6 RN4.8@45.2,84.6 ; v2@45.7,93.9 46,93.6 52.8,93.6 53.5,94.3 68.9,94.3 71.6,97 71.6,97.4 72.1,97.9 72.1,99.1 v2(72.1,101)
BUS_NBE3: RN3.6 RN5.7 U4.E17 U8.39 U12.40 | length 127.8
  Top Layer w0.2: U4.E17@42.2,45.9 v1(42.7,46.4)
  MidLayer1 w0.127: v2(44.9,94.1) 45.4,93.6 v2(58.8,93.6)
  MidLayer2 w0.127: v2(42.6,97.8) 42.6,96.4 v2(44.9,94.1) ; v1(42.7,46.4) 43.2,46.9 43.2,49.5 43.8,50.1 43.8,51.5 43.8,51.8 43.8,52.1 44.5,52.8 44.5,53.6 45,54.1 46.1,54.1 47.2,55.2 48.4,56.4 50.1,56.4 51.4,57.7 51.4,67.8 51.7,68.1 51.7,68.4 54.3,71 54.3,75.4 55.7,76.8 55.7,80.6 56.7,81.6 62.4,81.6 62.8,81.2 69.8,81.2 71,82.4 73.1,82.4 73.4,82.7 73.4,84.1 74.1,84.8 74.1,85.8 74.5,86.2 74.5,89.2 74.2,89.5 74.2,90.8 73.5,91.5 73.5,95.25 73.2,95.55 73.2,97.4 73.4,97.6 73.4,98.2 72.9,98.7 v2(72.9,100.4)
  MidLayer3 w0.127: v1@41.695,102.5 43.1,101.095 43.1,98.3 v2(42.6,97.8)
  Bottom Layer w0.127: RN3.6@40.29,102.5 v1(41.65,102.5) RN5.7@42.575,102.5 RN5.7@42.61,102.5 ; v2(42.6,97.8) U8.39@42.6,99.1 ; v2(58.8,93.6) 59.9,92.5 68.7,92.5 72.6,96.4 72.6,97.4 72.4,97.6 72.4,98.1 72.9,98.6 72.9,99.1 v2(72.9,100.4)
BUS_NOE: U3.G2 U4.A20 U11.41 U12.41 | length 97.9
  Top Layer w0.127: U4.A20@45.2,49.9 45.2,51.5 45.2,51.8 45.2,54.4 46.3,55.5 46.3,57.4 46.6,57.7 46.6,57.9 52.5,63.8 52.5,68.8 54,70.3 54,75 54.4,75.4 54.4,79.2 56.3,81.1 56.9,81.1 57.2,80.8 v1@57.2,80.125 ; v1@57.3,80.025 57.3,80.1 v1@57.3,80.125 ; v2(60.1,97.8) U11.41@60.1,99.1
  Top Layer w0.2: v1@57.2,80.125 57.213,80.113 57.3,80.025 U3.G2@57.7,79.625
  MidLayer3 w0.127: v2(73.7,100.4) 73.7,97.9 74.7,96.9 74.7,90.4 74.3,90 74.3,89.5 74.5,89.3 74.5,86.2 74.1,85.8 74.1,84.2 73.9,84 v1(73.9,83.5)
  MidLayer4 w0.127: v1(57.2,80.1) 57.2,82.9 58.5,84.2 73.2,84.2 v1(73.9,83.5) ; v2(60.1,97.8) 60.1,96.9 60.3,96.7 73.9,96.7 74.2,97 74.2,97.4 73.7,97.9 v2(73.7,100.4)
  Bottom Layer w0.127: U12.41@73.7,99.1 v2(73.7,100.4)
BUS_NWE: RN1.7 RN4.6 U3.A5 U4.H26 U7.16 U8.16 U11.17 U12.17 | length 121.6
  Top Layer w0.127: U7.16@45.8,87.7 v2(45.8,89.6) ; U7.16@45.8,87.9 45.8,87.2 45.3,86.7 45.3,86.2 45.7,85.8 48.1,85.8 48.7,85.2 62.7,85.2 v1(63.3,85.8) ; U4.H26@51.2,42.9 52.8,42.9 53.1,42.9 55.6,42.9 57.8,45.1 57.8,53.8 60.8,56.8 60.8,57.5 61,57.7 61,58.1 62,59.1 62,66.3 62.7,67 62.7,70.9 65,73.2 65,75.4 63.775,76.625 U3.A5@63.7,76.625 ; U11.17@70.5,87.7 70.5,88.2 71,88.7 71,89.1 70.8,89.3 70.8,89.8 v1(71.3,90.3)
  MidLayer1 w0.127: v1(64.2,76.1) 63.7,76.1 63.2,76.6 62,76.6 61.7,76.9 61.7,78.3 61.4,78.6 60.9,78.6 60.7,78.8 60.7,79.3 61,79.6 61.4,79.6 61.7,79.9 61.7,80.3 62,80.6 63.3,80.6 63.9,81.2 69.3,81.2 71.1,83 71.1,89 70.8,89.3 70.8,89.8 v1(71.3,90.3)
  MidLayer2 w0.127: v2(42.6,89) 42.6,87.2 43.1,86.7 43.1,86.3 42.9,86.1 42.9,84.4 v1@43.7,83.6
  MidLayer4 w0.127: v2(42.6,89) 43.7,89 44.3,89.6 v2(45.8,89.6) ; v1(63.3,85.8) 62.4,85.8 62,86.2 62,86.7 63.6,88.3 69.2,88.3 v1@71.25,90.35
  Bottom Layer w0.127: U8.16@42.6,87.7 v2(42.6,89) ; RN1.7@42.88,83.6 45.2,83.6 RN4.6@45.21,83.6 ; v1(63.3,85.8) U12.17@63.3,87.7
  other v1: 43.8,83.6
BUS_SDRAM_CKE: RN3.7 RN5.6 U4.G17 U7.37 U8.37 | length 83.5
  Top Layer w0.127: v2(47.4,97.8) U7.37@47.4,99.1
  Top Layer w0.2: U4.G17@42.2,43.9 v1(42.7,44.4)
  MidLayer3 w0.127: v2(41,100.3) 41,101 41.12,101.12 v1@41.12,102 ; v2(47.4,97.8) 47.4,97 49.5,94.9 53.3,94.9 55.7,92.5 v1(55.7,86.3)
  MidLayer4 w0.127: v2(41,100.3) 41.6,100.9 42.8,100.9 44.6,99.1 46.1,99.1 v2(47.4,97.8) ; v1(42.7,44.4) 43.2,44.9 43.2,49.1 44.2,50.1 44.2,51.5 44.2,51.8 44.2,52.6 44.4,52.8 44.4,57.3 43.9,57.8 43.9,66.2 46.1,68.4 46.1,68.7 48.6,71.2 53.1,71.2 54.1,72.2 54.1,82.5 55.7,84.1 v1(55.7,86.3)
  Bottom Layer w0.127: U8.37@41,99.1 v2(41,100.3) ; v1@41.075,102 40.29,102 RN5.6@42.575,102 RN5.6@42.61,102
  other v1: 41.1,102
BUS_SDRAM_CLK: NT4.2 RN3.8 RN5.5 U4.F13 U7.38 U8.38 | length 86.7
  Top Layer w0.127: NT4.2@39.4,54.471 39.4,55 39.7,55.3 v1(40.2,55.3) ; v2(46.6,97.2) U7.38@46.6,99.1
  Top Layer w0.2: v1(37.7,45.4) U4.F13@38.2,44.9
  MidLayer3 w0.127: v1(37.7,45.4) 37.2,45.9 37.2,49.699 36.195,50.703 36.195,53.177 36.854,53.835 36.854,54.456 37.698,55.3 v1(40.2,55.3) ; v2(46.6,97.2) 49.2,94.6 53.1,94.6 55.1,92.6 v1(55.1,85.8)
  MidLayer4 w0.127: v1(40.2,55.3) 41,55.3 43.459,57.76 43.459,67.309 47.65,71.5 53,71.5 53.8,72.3 53.8,82.6 55.4,84.2 55.4,85.1 55.1,85.4 v1(55.1,85.8) ; v2(41.8,100.3) 43.3,98.8 45.7,98.8 46.6,97.9 v2(46.6,97.2)
  Bottom Layer w0.127: RN3.8@40.29,101.5 RN5.5@42.575,101.5 RN5.5@42.61,101.5 ; U8.38@41.8,99.1 41.8,101.5
BUS_SDRAM_FEEDBACK: NT4.1 U4.B15 | length 6.3
  Top Layer w0.127: NT4.1@39.395,53.962 v1(39.395,53.391) 40.208,53.391 40.4,53.199 40.4,51.8 40.4,51.5 40.4,50.6 40.7,50.3 40.7,49.4 U4.B15@40.2,48.9
BUS_SDRAM_NCAS: RN2.7 RN6.6 U4.G18 U7.17 U8.17 | length 80
  Top Layer w0.127: U7.17@46.6,87.7 46.6,88.9 v1(46.6,89)
  Top Layer w0.2: U4.G18@43.2,43.9 v1(43.7,44.4)
  MidLayer3 w0.127: v1@36.175,83.6 37.1,83.6 38.6,85.1 41.1,85.1 v2(41.8,85.8)
  MidLayer4 w0.127: v2(41.8,85.8) 41.8,86.4 42.4,87 44.6,87 v1(46.6,89) 48.017,87.3 55.4,87.3 56.2,86.5 56.2,84.1 54.4,82.3 54.4,72.1 53.2,70.9 48.8,70.9 46.4,68.5 46.4,68.1 46.6,67.9 46.6,59.8 45.1,58.3 45.1,57.8 44.7,57.4 44.7,51.8 44.7,51.5 44.7,50.2 44.2,49.7 44.2,44.9 v1(43.7,44.4)
  Bottom Layer w0.127: RN2.7@35.39,83.6 36.175,83.6 RN6.6@37.675,83.6 RN6.6@37.71,83.6 ; v2(41.8,85.8) U8.17@41.8,87.7
  other v1: 36.2,83.6
BUS_SDRAM_NCS: RN2.5 RN6.8 U4.G19 U7.19 U8.19 | length 84.5
  Top Layer w0.127: U7.19@48.2,87.7 v2(48.2,89)
  Top Layer w0.2: U4.G19@44.2,43.9 v1(44.7,44.4)
  MidLayer3 w0.127: v1(36.2,84.6) 36.7,84.6 37.047,84.947 37.8,85.7 40.1,85.7 40.7,86.3 40.7,87.3 40.2,87.8 v2(40.2,89.6)
  MidLayer4 w0.127: v2(40.2,89.6) 40.2,88.9 41.2,87.9 44.8,87.9 46.4,89.5 46.8,89.5 47.3,89 v2(48.2,89) 49.6,87.6 55.5,87.6 56.5,86.6 56.5,83.9 55.4,82.8 55.4,72.7 53.3,70.6 49.6,70.6 47.4,68.4 47.4,68.1 47.2,67.9 47.2,59.8 45.5,58.1 45.5,57.8 45.8,57.5 45.8,56.7 45.2,56.1 45.2,51.8 45.2,51.5 45.2,44.9 v1(44.7,44.4)
  Bottom Layer w0.127: v1(36.2,84.6) 35.39,84.6 RN6.8@37.675,84.6 RN6.8@37.7,84.6 ; U8.19@40.2,87.7 v2(40.2,89.6)
BUS_SDRAM_NRAS: RN2.6 RN6.7 U4.G20 U7.18 U8.18 | length 79.9
  Top Layer w0.127: U7.18@47.4,87.7 v1(47.4,89.6)
  Top Layer w0.2: U4.G20@45.2,43.9 v1(45.7,44.4)
  MidLayer1 w0.127: v2(41,85.8) 42.9,87.7 44.6,87.7 46.5,89.6 v1(47.4,89.6)
  MidLayer3 w0.127: v1(36.75,84.1) 38.05,85.4 40.6,85.4 v2(41,85.8)
  MidLayer4 w0.127: v1(45.7,44.4) 46.2,44.9 46.2,51.5 46.2,51.8 46.2,57.3 48.3,59.4 48.3,67.8 48,68.1 48,68.6 49.7,70.3 53.4,70.3 55.7,72.6 55.7,82.6 56.8,83.7 56.8,86.7 55.6,87.9 50,87.9 48.3,89.6 v1(47.4,89.6) v1@47.2,89.7
  Bottom Layer w0.127: RN2.6@35.39,84.1 v1(36.75,84.1) RN6.7@37.675,84.1 RN6.7@37.71,84.1 ; v2(41,85.8) U8.18@41,87.7
BUS_SRAM_NCS: U4.G9 U11.6 U12.6 | length 92.6
  Top Layer w0.127: U11.6@61.7,87.7 61.7,89 v2(61.7,89.5)
  Top Layer w0.2: v1(33.7,44.4) U4.G9@34.2,43.9
  MidLayer2 w0.127: v1(33.7,44.4) 34.2,44.9 35.1,44.9 35.2,45 35.2,51.5 35.2,51.8 35.2,55.2 36.8,56.8 36.8,57.5 37.8,58.5 41.1,58.5 43,60.4 43,66.8 45.4,69.2 51.5,69.2 53.7,71.4 53.7,75.7 54.4,76.4 54.4,80.125 56.475,82.2 62.6,82.2 63,81.8 68.8,81.8 72.2,85.2 72.2,85.975 v2(72.625,86.4)
  MidLayer4 w0.127: v2(61.7,89.5) 61.7,86.5 61.2,86 61.2,85.5 61.9,84.8 71.025,84.8 v2(72.625,86.4)
  Bottom Layer w0.127: U12.6@72.1,87.7 72.1,87.209 72.363,86.946 72.363,86.663 v2(72.625,86.4)
BUZZER: HDR_B1.40 U4.AF18 | length 9.7
  Top Layer w0.127: U4.AF18@43.2,24.9 43.2,23.3 43.2,23 43.2,22.1 43.7,21.6 v2(43.7,17.5)
  Bottom Layer w0.2: HDR_B1.40@43.7,15.4 v2(43.7,17.5)
CAN_RXD: HDR_T1.14 U4.A10 | length 21.6
  Top Layer w0.127: v2(33.3,67.7) 33.3,62.8 37,59.1 37,57.7 36.7,57.4 36.7,56.9 35.8,56 35.8,52.9 35.2,52.3 35.2,51.8 35.2,51.5 U4.A10@35.2,49.9
  Bottom Layer w0.2: HDR_T1.14@33.3,66.2 v2(33.3,67.7)
CAN_TXD: HDR_T1.16 U4.B12 | length 24.2
  Top Layer w0.127: v2(34.1,68.3) 34.1,62.6 37.6,59.1 37.6,57.7 37.9,57.4 37.9,57.2 36.2,55.5 36.2,51.8 36.2,51.5 36.2,50.7 36.7,50.2 36.7,49.4 U4.B12@37.2,48.9
  Bottom Layer w0.2: HDR_T1.16@34.1,66.2 v2(34.1,68.3)
CCLK: R17.2 U4.G14 | length 17.1
  Top Layer w0.2: U4.G14@39.2,43.9 39.687,44.412 v1@39.7,44.425
  Bottom Layer w0.127: v1(39.7,44.4) 40.2,43.9 50.4,43.9 51.3,43 51.3,40.2 51.888,39.612 R17.2@52.451,39.612
COMP: C80.2 U5.6 | length 3.1
  Top Layer w0.35: U5.6@71.744,44.659 74.734,44.659 C80.2@74.8,44.725
DAU_RESET_SW: HDR_B1.38 U4.AC15 | length 14
  Top Layer w0.2: U4.AC15@40.2,27.9 v1(40.7,27.4)
  MidLayer1 w0.127: v1(40.7,27.4) 40.2,26.9 40.2,23.3 40.2,23 40.2,22 42.9,19.3 v2(42.9,16.9)
  Bottom Layer w0.2: HDR_B1.38@42.9,15.4 v2(42.9,16.9)
DAU_TFT_BLIGHT: HDR_B1.91 U4.AA14 | length 48.9
  Top Layer w0.2: U4.AA14@39.2,29.9 v1(39.7,29.4)
  MidLayer3 w0.127: v1(39.7,29.4) 40.2,28.9 40.2,23.3 40.2,23 40.2,21.2 40.5,20.9 40.5,18.4 38.6,16.5 38.6,12.4 40.9,10.1 62.3,10.1 64.5,7.9 v2(64.5,7.1)
  Bottom Layer w0.2: v2(64.5,7.1) HDR_B1.91@64.5,8.6
DAU_TFT_BLUE0: HDR_B1.62 U4.AF23 | length 11.3
  Top Layer w0.127: U4.AF23@48.2,24.9 48.2,23.3 48.2,23 48.2,21.8 52.5,17.5 v2(52.5,16.9)
  Bottom Layer w0.2: HDR_B1.62@52.5,15.4 v2(52.5,16.9)
DAU_TFT_BLUE1: HDR_B1.64 U4.AE23 | length 12.6
  Top Layer w0.127: U4.AE23@48.2,25.9 48.7,25.4 48.7,23.3 48.7,23 48.7,22.1 v2@53.3,17.5
  Bottom Layer w0.2: HDR_B1.64@53.3,15.4 v2(53.3,17.5)
DAU_TFT_BLUE2: HDR_B1.66 U4.W7 | length 41.1
  Top Layer w0.2: v1(31.7,31.4) U4.W7@32.2,31.9
  MidLayer4 w0.127: v1(31.7,31.4) 31.2,30.9 30.4,30.9 30.2,30.7 30.2,23.3 30.2,23 30.2,19.1 33.2,16.1 53.3,16.1 v2(54.1,16.9)
  Bottom Layer w0.2: HDR_B1.66@54.1,15.4 v2(54.1,16.9)
DAU_TFT_BLUE3: HDR_B1.68 U4.V7 | length 47.1
  Top Layer w0.2: v1(31.7,32.4) U4.V7@32.2,32.9
  MidLayer4 w0.127: v1(31.7,32.4) 31.2,31.9 29.5,31.9 29.2,31.6 29.2,23.3 29.2,23 29.2,22.7 28.6,22.1 28.6,19.1 31.9,15.8 53.8,15.8 54.9,16.9 v2(54.9,17.5)
  Bottom Layer w0.2: HDR_B1.68@54.9,15.4 v2(54.9,17.5)
DAU_TFT_BLUE4: HDR_B1.70 U4.U7 | length 49.8
  Top Layer w0.2: v1(31.7,33.4) U4.U7@32.2,33.9
  MidLayer4 w0.127: v1(31.7,33.4) 31.2,32.9 28.5,32.9 28.2,32.6 28.2,23.3 28.2,23 28.2,17.9 30.6,15.5 54.3,15.5 v2(55.7,16.9)
  Bottom Layer w0.2: HDR_B1.70@55.7,15.4 v2(55.7,16.9)
DAU_TFT_CL1: HDR_B1.88 U4.J7 | length 84
  Top Layer w0.2: v1(31.7,42.4) U4.J7@32.2,41.9
  MidLayer4 w0.127: v1(31.7,42.4) 31.2,42.9 27.2,42.9 26.7,43.4 24.6,43.4 24.3,43.4 22.4,43.4 20.8,41.8 20.8,20 28,12.8 58.8,12.8 62.9,16.9 v2(62.9,17.5)
  Bottom Layer w0.2: HDR_B1.88@62.9,15.4 v2(62.9,17.5)
DAU_TFT_CL2: HDR_B1.90 U4.G7 | length 86.1
  Top Layer w0.2: v1(31.7,44.4) U4.G7@32.2,43.9
  MidLayer4 w0.127: v1(31.7,44.4) 31.2,43.9 24.6,43.9 24.3,43.9 22.5,43.9 20.4,41.8 20.4,20 27.9,12.5 59.3,12.5 v2(63.7,16.9)
  Bottom Layer w0.2: v2(63.7,16.9) HDR_B1.90@63.7,15.4 v2(63.7,16.9)
DAU_TFT_CL3: HDR_B1.92 U4.G8 | length 89.1
  Top Layer w0.2: v1(32.7,44.4) U4.G8@33.2,43.9
  MidLayer4 w0.127: v1(32.7,44.4) 32.2,44.9 24.6,44.9 24.3,44.9 23.1,44.9 20,41.8 20,20 27.8,12.2 59.8,12.2 64.5,16.9 v2(64.5,17.5)
  Bottom Layer w0.2: HDR_B1.92@64.5,15.4 v2(64.5,17.5)
DAU_TFT_DISP_ON: HDR_B1.89 U4.AA13 | length 48.4
  Top Layer w0.2: v1(37.7,29.4) U4.AA13@38.2,29.9
  MidLayer3 w0.127: v1(37.7,29.4) 37.2,28.9 37.2,23.3 37.2,23 37.2,18.4 36.8,18 36.8,17.3 37.1,17 37.1,13.4 40.7,9.8 61.8,9.8 63.7,7.9 v2(63.7,7.1)
  Bottom Layer w0.2: v2(63.7,7.1) HDR_B1.89@63.7,8.6
DAU_TFT_GREEN0: HDR_B1.72 U4.T7 | length 57.4
  Top Layer w0.2: v1(31.7,34.4) U4.T7@32.2,34.9
  MidLayer4 w0.127: v1(31.7,34.4) 31.3,33.9 27.4,33.9 27.1,33.9 25.1,31.9 25.1,19.5 29.4,15.2 54.8,15.2 56.5,16.9 v2(56.5,17.5)
  Bottom Layer w0.2: HDR_B1.72@56.5,15.4 v2(56.5,17.5)
DAU_TFT_GREEN1: HDR_B1.74 U4.R7 | length 59.2
  Top Layer w0.2: v1(31.7,35.4) U4.R7@32.2,35.9
  MidLayer4 w0.127: v1(31.7,35.4) 31.2,34.9 26.2,34.9 24.8,33.5 24.8,19.3 29.2,14.9 55.3,14.9 v2(57.3,16.9)
  Bottom Layer w0.2: HDR_B1.74@57.3,15.4 v2(57.3,16.9)
DAU_TFT_GREEN2: HDR_B1.76 U4.P7 | length 62.9
  Top Layer w0.2: v1(31.7,36.4) U4.P7@32.2,36.9
  MidLayer4 w0.127: v1(31.7,36.4) 31.2,35.9 26.4,35.9 24.5,34 24.5,19.125 24.504,19.121 29.025,14.6 55.8,14.6 58.1,16.9 v2(58.1,17.5)
  Bottom Layer w0.2: HDR_B1.76@58.1,15.4 v2(58.1,17.5)
DAU_TFT_GREEN3: HDR_B1.78 U4.T8 | length 68
  Top Layer w0.2: v1(32.7,34.4) U4.T8@33.2,34.9
  MidLayer4 w0.127: 28.9,14.3 56.3,14.3 v2(58.9,16.9) ; 28.9,14.304 24.2,19.004 24.2,34.4 26.7,36.9 33,36.9 33.2,36.7 33.2,34.9 v1(32.7,34.4)
  Bottom Layer w0.2: HDR_B1.78@58.9,15.4 v2(58.9,16.9)
DAU_TFT_GREEN4: HDR_B1.80 U4.N7 | length 70.4
  Top Layer w0.2: v1(31.7,38.4) U4.N7@32.2,37.9
  MidLayer4 w0.127: v1(31.7,38.4) 31.2,38.9 26.3,38.9 24.1,38.9 23.9,38.7 23.9,18.8 28.7,14 56.8,14 59.7,16.9 v2(59.7,17.5)
  Bottom Layer w0.2: HDR_B1.80@59.7,15.4 v2(59.7,17.5)
DAU_TFT_GREEN5: HDR_B1.82 U4.M7 | length 71.7
  Top Layer w0.2: v1(31.7,39.4) U4.M7@32.2,38.9
  MidLayer4 w0.127: v1(31.7,39.4) 31.2,39.9 24.3,39.9 23.6,39.2 23.6,18.6 28.5,13.7 57.3,13.7 v2(60.5,16.9)
  Bottom Layer w0.2: HDR_B1.82@60.5,15.4 v2(60.5,16.9)
DAU_TFT_IRQ: HDR_B1.81 U4.AA9 | length 48.2
  Top Layer w0.2: v1(33.7,29.4) U4.AA9@34.2,29.9
  MidLayer3 w0.127: v1(33.7,29.4) 33.2,28.9 33.2,25.7 33.4,25.5 33.4,23.3 33.4,23 33.4,22.8 32.8,22.2 32.8,18.1 33.8,17.1 33.8,14.7 39.9,8.6 59.8,8.6 60.5,7.9 v2(60.5,7.1)
  Bottom Layer w0.2: v2(60.5,7.1) HDR_B1.81@60.5,8.6
DAU_TFT_M: HDR_B1.87 U4.AA12 | length 48.2
  Top Layer w0.2: v1(36.7,29.4) U4.AA12@37.2,29.9
  MidLayer3 w0.127: v1(36.7,29.4) 36.2,28.9 36.2,23.3 36.2,23 36.2,17.3 35.9,17 35.9,14.1 40.5,9.5 61.3,9.5 62.9,7.9 v2(62.9,7.1)
  Bottom Layer w0.2: v2(62.9,7.1) HDR_B1.87@62.9,8.6
DAU_TFT_MUX: HDR_B1.85 U4.AA11 | length 48.3
  Top Layer w0.2: v1(35.7,29.4) U4.AA11@36.2,29.9
  MidLayer3 w0.127: v1(35.7,29.4) 35.2,28.9 35.2,23.3 35.2,23 35.2,21.003 35.692,20.511 35.692,19.344 35.2,18.852 35.2,17.3 35.5,17 35.5,14 40.3,9.2 60.8,9.2 62.1,7.9 v2(62.1,7.1)
  Bottom Layer w0.2: v2(62.1,7.1) HDR_B1.85@62.1,8.6
DAU_TFT_POL: HDR_B1.83 U4.AA10 | length 48
  Top Layer w0.2: v1(34.7,29.4) U4.AA10@35.2,29.9
  MidLayer3 w0.127: v1(34.7,29.4) 34.2,28.9 34.2,23.3 34.2,23 34.2,18.437 34.7,17.937 34.7,17.4 34.4,17.1 34.4,14.6 40.1,8.9 60.3,8.9 61.3,7.9 v2(61.3,7.1)
  Bottom Layer w0.2: v2(61.3,7.1) HDR_B1.83@61.3,8.6
DAU_TFT_RED0: HDR_B1.52 U4.Y7 | length 33.3
  Top Layer w0.2: v1(31.7,30.4) U4.Y7@32.2,30.9
  MidLayer4 w0.127: v1(31.7,30.4) 31.2,29.9 31.2,23.3 31.2,23 31.2,19.7 34.5,16.4 48.2,16.4 48.5,16.7 v2(48.5,17.5)
  Bottom Layer w0.2: HDR_B1.52@48.5,15.4 v2(48.5,17.5)
DAU_TFT_RED1: HDR_B1.54 U4.Y8 | length 31.5
  Top Layer w0.2: v1(32.7,30.4) U4.Y8@33.2,30.9
  MidLayer4 w0.127: v1(32.7,30.4) 32.2,29.9 32.2,25.1 31.8,24.7 31.8,23.3 31.8,23 31.8,21 34.801,17.998 48.801,17.998 49.3,17.5 v2(49.3,16.9)
  Bottom Layer w0.2: HDR_B1.54@49.3,15.4 v2(49.3,16.9)
DAU_TFT_RED2: HDR_B1.56 U4.Y9 | length 32.1
  Top Layer w0.2: v1(33.7,30.4) U4.Y9@34.2,30.9
  MidLayer4 w0.127: v1(33.7,30.4) 33.2,29.9 33.2,25.4 32.2,24.4 32.2,23.3 32.2,23 32.2,21.2 32.999,20.401 37.799,20.401 39,19.2 39.9,18.3 49.3,18.3 v2(50.1,17.5)
  Bottom Layer w0.2: HDR_B1.56@50.1,15.4 v2(50.1,17.5)
DAU_TFT_RED3: HDR_B1.58 U4.Y10 | length 28.2
  Top Layer w0.2: v1(34.7,30.4) U4.Y10@35.2,30.9
  MidLayer4 w0.127: v1(34.7,30.4) 34.2,29.9 34.2,25.06 34.933,24.326 37.414,24.326 43.141,18.6 49.8,18.6 50.9,17.5 v2(50.9,16.9)
  Bottom Layer w0.2: HDR_B1.58@50.9,15.4 v2(50.9,16.9)
DAU_TFT_RED4: HDR_B1.60 U4.AF22 | length 11.4
  Top Layer w0.127: U4.AF22@47.2,24.9 47.2,23.3 47.2,23 47.2,22.4 51.7,17.9 v2(51.7,17.5)
  Bottom Layer w0.2: HDR_B1.60@51.7,15.4 v2(51.7,17.5)
DAU_TFT_STH: HDR_B1.86 U4.K7 | length 80.9
  Top Layer w0.2: v1(31.7,41.4) U4.K7@32.2,40.9
  MidLayer4 w0.127: v1(31.7,41.4) 31.2,41.9 27,41.9 26,42.9 24.6,42.9 24.3,42.9 22.3,42.9 21.2,41.8 21.2,20 28.1,13.1 58.3,13.1 v2(62.1,16.9)
  Bottom Layer w0.2: HDR_B1.86@62.1,15.4 v2(62.1,16.9)
DAU_TFT_STV: HDR_B1.84 U4.L7 | length 76.9
  Top Layer w0.2: v1(31.7,40.4) U4.L7@32.2,39.9
  MidLayer4 w0.127: v1(31.7,40.4) 31.3,40.9 27.4,40.9 24.6,40.9 24.3,40.9 21.6,38.2 21.6,20.1 28.3,13.4 57.8,13.4 61.3,16.9 v2(61.3,17.5)
  Bottom Layer w0.2: HDR_B1.84@61.3,15.4 v2(61.3,17.5)
DIP0: HDR_B1.22 U4.AD12 | length 11.8
  Top Layer w0.2: v1(36.7,26.4) U4.AD12@37.2,26.9
  MidLayer1 w0.127: v2(36.5,16.9) 36.5,17.6 36.7,17.8 36.7,23 36.7,23.3 v1(36.7,26.4)
  Bottom Layer w0.2: HDR_B1.22@36.5,15.4 v2(36.5,16.9)
DIP1: HDR_B1.24 U4.AC12 | length 13.1
  Top Layer w0.2: v1(36.7,27.4) U4.AC12@37.2,27.9
  MidLayer1 w0.127: v1(36.7,27.4) 37.2,26.9 37.2,23.3 37.2,23 37.2,21.9 37.3,21.8 v2(37.3,17.5) v2@37.2,17.6
  Bottom Layer w0.2: HDR_B1.24@37.3,15.4 v2(37.3,17.5)
DIP2: HDR_B1.26 U4.AD13 | length 11.9
  Top Layer w0.2: v1(37.7,26.4) U4.AD13@38.2,26.9
  MidLayer1 w0.127: v1(37.7,26.4) 37.7,23.3 37.7,23 37.7,18 38.1,17.6 v2(38.1,16.9)
  Bottom Layer w0.2: HDR_B1.26@38.1,15.4 v2(38.1,16.9)
DIP3: HDR_B1.28 U4.AF12 | length 10.2
  Top Layer w0.127: U4.AF12@37.2,24.9 37.2,24.2 37.9,23.5 37.9,22.8 37.9,22.5 37.9,18.559 38.9,17.559 v2(38.9,17.5)
  Bottom Layer w0.2: HDR_B1.28@38.9,15.4 v2(38.9,17.5)
DIP4: HDR_B1.30 U4.AC13 | length 13.9
  Top Layer w0.2: v1(37.7,27.4) U4.AC13@38.2,27.9
  MidLayer1 w0.127: v1(37.7,27.4) 38.2,26.9 38.2,26.1 38,25.9 38,23.3 38,23 38,19.8 38.5,19.3 38.916,19.3 39.3,18.916 39.3,18.6 39.7,18.2 v2(39.7,16.9)
  Bottom Layer w0.2: HDR_B1.30@39.7,15.4 v2(39.7,16.9)
DIP5: HDR_B1.32 U4.AC6 | length 28.9
  Top Layer w0.2: v1(30.7,27.4) U4.AC6@31.2,27.9
  MidLayer1 w0.127: v1(30.7,27.4) 30.2,26.9 30.2,25 29.9,24.7 29.9,23.3 29.9,23 29.9,19.2 28,17.3 28,16.6 28.9,15.7 39.7,15.7 40.5,16.5 v2(40.5,17.5)
  Bottom Layer w0.2: HDR_B1.32@40.5,15.4 v2(40.5,17.5)
DIP6: HDR_B1.34 U4.AC14 | length 13.8
  Top Layer w0.2: U4.AC14@39.2,27.9 v1(39.7,27.4)
  MidLayer1 w0.127: v1(39.7,27.4) 39.2,26.9 39.2,23.3 39.2,23 39.2,21.7 41.3,19.6 v2(41.3,16.9)
  Bottom Layer w0.2: HDR_B1.34@41.3,15.4 v2(41.3,16.9)
DIP7: HDR_B1.36 U4.AD14 | length 12.7
  Top Layer w0.2: U4.AD14@39.2,26.9 v1(39.7,26.4)
  MidLayer1 w0.127: v1(39.7,26.4) 39.7,23.3 39.7,23 39.7,21.9 42.1,19.5 v2(42.1,17.5)
  Bottom Layer w0.2: HDR_B1.36@42.1,15.4 v2(42.1,17.5)
DONE: R16.2 U4.H14 | length 18
  Top Layer w0.2: U4.H14@39.2,42.9 v1(39.7,43.4)
  Bottom Layer w0.127: v1(39.7,43.4) 39.2,43.9 39.2,44.7 39.4,44.9 50.8,44.9 51.7,44 51.7,42.1 51.938,41.862 R16.2@52.451,41.862 ; R16.2@52.451,41.9 R16.2@52.5,41.9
